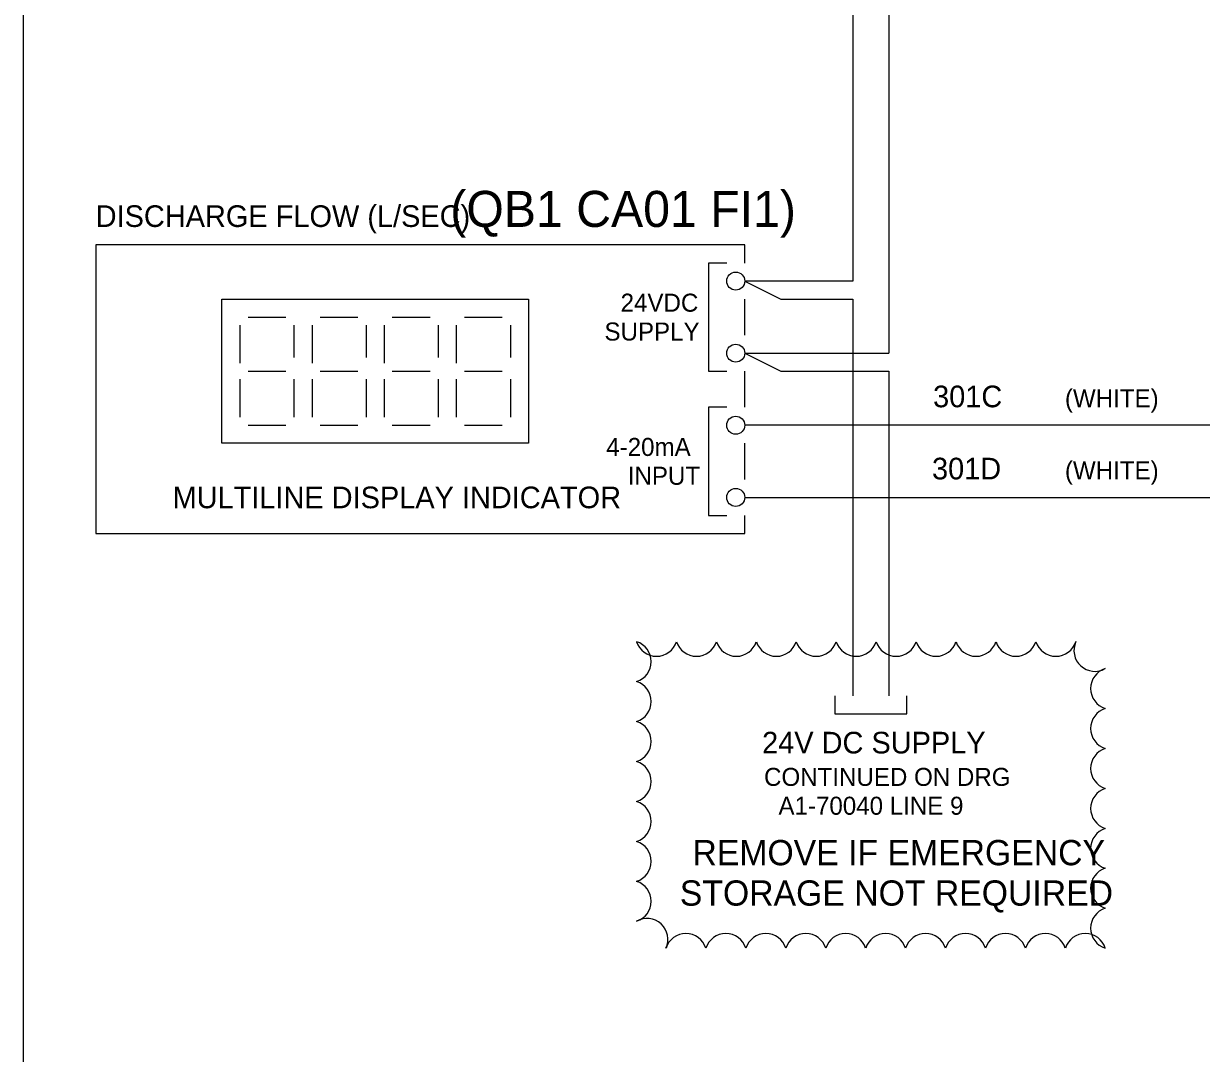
# Model space of a CAD drawing. Extents: x 0 to 841, y 0 to 594.
# Drawn here: x 425 to 588.3, y 162.9 to 305.7 of the extents above; entities that cross this region are included whole.
import ezdxf

# ---------------------------------------------------------------- set-up
doc = ezdxf.new("R2010")
doc.units = 0
for name, color, linetype in [('Level 1', 7, 'Continuous'), ('Level 10', 7, 'Continuous'), ('Level 2', 7, 'Continuous')]:
    doc.layers.add(name, color=color, linetype=linetype)

msp = doc.modelspace()

# ---------------------------------------------------------------- linework, layer by layer
at = {"layer": 'Level 1'}
for p, q in [((425, 57.5), (425, 572.5)), ((540, 392.5), (540, 270)), ((545, 382.5), (545, 260)), ((540, 270), (525, 270)), ((525, 270), (530, 267.5)), ((530, 267.5), (540, 267.5)), ((540, 267.5), (540, 212.5)), ((525, 260), (545, 260)), ((525, 260), (530, 257.5)), ((530, 257.5), (545, 257.5)), ((545, 257.5), (545, 212.5)), ((730, 250), (525, 250)), ((525, 240), (720, 240))]:
    msp.add_line(p, q, dxfattribs=at)
for points in [[(522.5, 272.5), (520, 272.5), (520, 257.5), (522.5, 257.5)], [(522.5, 252.5), (520, 252.5), (520, 237.5), (522.5, 237.5)], [(537.5, 212.5), (537.5, 210), (547.5, 210), (547.5, 212.5)]]:
    msp.add_lwpolyline(points, dxfattribs=at)
msp.add_lwpolyline([(452.5, 267.5), (495, 267.5), (495, 247.5), (452.5, 247.5)], close=True, dxfattribs=at)
for centre, start, end in [((512.77, 220.87), 197.5, 342.5), ((509.13, 217.23), 287.5, 72.5), ((518.31, 220.87), 197.5, 342.5), ((523.84, 220.87), 197.5, 342.5), ((529.38, 220.87), 197.5, 342.5), ((534.92, 220.87), 197.5, 342.5), ((540.46, 220.87), 197.5, 342.5), ((546, 220.87), 197.5, 342.5), ((551.53, 220.87), 197.5, 342.5), ((557.07, 220.87), 197.5, 342.5), ((562.61, 220.87), 197.5, 342.5), ((568.15, 220.87), 197.5, 342.5), ((573.55, 218.78), 155.0543, 300.0543), ((575.87, 213.5), 107.5, 252.5), ((509.13, 211.69), 287.5, 72.5), ((575.87, 207.96), 107.5, 252.5), ((509.13, 206.16), 287.5, 72.5), ((575.87, 202.42), 107.5, 252.5), ((509.13, 200.62), 287.5, 72.5), ((575.87, 196.88), 107.5, 252.5), ((509.13, 195.08), 287.5, 72.5), ((575.87, 191.34), 107.5, 252.5), ((509.13, 189.54), 287.5, 72.5), ((575.87, 185.81), 107.5, 252.5), ((509.13, 184), 287.5, 72.5), ((575.87, 180.27), 107.5, 252.5), ((511.45, 178.72), 335.0543, 120.0543), ((516.85, 176.63), 17.5, 162.5), ((522.39, 176.63), 17.5, 162.5), ((527.93, 176.63), 17.5, 162.5), ((533.47, 176.63), 17.5, 162.5), ((539, 176.63), 17.5, 162.5), ((544.54, 176.63), 17.5, 162.5), ((550.08, 176.63), 17.5, 162.5), ((555.62, 176.63), 17.5, 162.5), ((561.16, 176.63), 17.5, 162.5), ((566.69, 176.63), 17.5, 162.5), ((572.23, 176.63), 17.5, 162.5)]:
    msp.add_arc(centre, 2.9, start, end, dxfattribs=at)
at = {"layer": 'Level 10'}
for centre in [(523.75, 270), (523.75, 260), (523.75, 250), (523.75, 240)]:
    msp.add_circle(centre, 1.25, dxfattribs=at)
at = {"layer": 'Level 2'}
for p, q in [((456.13, 265), (461.37, 265)), ((466.13, 265), (471.37, 265)), ((476.13, 265), (481.37, 265)), ((486.13, 265), (491.37, 265)), ((455, 263.88), (455, 258.63)), ((462.5, 263.88), (462.5, 259.38)), ((465, 263.88), (465, 258.63)), ((472.5, 263.88), (472.5, 259.38)), ((475, 263.88), (475, 258.63)), ((482.5, 263.88), (482.5, 259.38)), ((485, 263.88), (485, 258.63)), ((492.5, 263.88), (492.5, 259.38)), ((456.13, 257.5), (461.37, 257.5)), ((466.13, 257.5), (471.37, 257.5)), ((476.13, 257.5), (481.37, 257.5)), ((486.13, 257.5), (491.37, 257.5)), ((455, 256.38), (455, 251.13)), ((462.5, 256.38), (462.5, 251.13)), ((465, 256.38), (465, 251.13)), ((472.5, 256.38), (472.5, 251.13)), ((475, 256.38), (475, 251.13)), ((482.5, 256.38), (482.5, 251.13)), ((485, 256.38), (485, 251.13)), ((492.5, 256.38), (492.5, 251.13)), ((456.13, 250), (461.37, 250)), ((466.13, 250), (471.37, 250)), ((476.13, 250), (481.37, 250)), ((486.13, 250), (491.37, 250))]:
    msp.add_line(p, q, dxfattribs=at)
for points in [[(525, 272.5), (525, 275), (435, 275), (435, 235)], [(525, 262.5), (525, 267.5)], [(525, 252.5), (525, 257.5)], [(525, 242.5), (525, 247.5)], [(435, 235), (525, 235), (525, 237.5)]]:
    msp.add_lwpolyline(points, dxfattribs=at)

# ---------------------------------------------------------------- texts
at = {"layer": 'Level 1'}
for s, height, p in [('(QB1 CA01 FI1)', 5, (484.17, 277.5)), ('DISCHARGE FLOW (L/SEC)', 3, (435, 277.5)), ('24VDC', 2.5, (507.79, 265.75)), ('SUPPLY', 2.5, (505.55, 261.75)), ('301C', 3, (551.12, 252.5)), ('(WHITE)', 2.5, (569.4, 252.5)), ('4-20mA', 2.5, (505.8, 245.75)), ('301D', 3, (550.97, 242.5)), ('(WHITE)', 2.5, (569.4, 242.5)), ('INPUT', 2.5, (508.78, 241.75)), ('24V DC SUPPLY', 3, (527.41, 204.5)), ('CONTINUED ON DRG', 2.5, (527.68, 200)), ('A1-70040 LINE 9', 2.5, (529.68, 196)), ('REMOVE IF EMERGENCY', 3.5, (517.75, 189)), ('STORAGE NOT REQUIRED', 3.5, (516, 183.4))]:
    msp.add_text(s, height=height, dxfattribs=at).set_placement(p)
at = {"layer": 'Level 2'}
msp.add_text('MULTILINE DISPLAY INDICATOR', height=3, dxfattribs=at).set_placement((445.66, 238.5))

doc.saveas('drawing.dxf')
